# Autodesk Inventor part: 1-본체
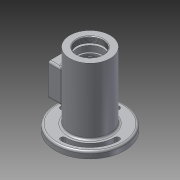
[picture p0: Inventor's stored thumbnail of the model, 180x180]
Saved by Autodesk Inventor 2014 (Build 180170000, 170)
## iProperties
Created: 2017-05
Part Number: 1-본체
Material: Aluminum 6061
Document SubType Name: Modeling
Designer: Administrator
Density: 2.71 g/cm^3
Appearance: Aluminum - Flat
Author: Administrator
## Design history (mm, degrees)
sketch "Sketch3"
  geometry: C1 r 31 at (0, 0); 1 further point
  constraints: 1 centre point, 1 coincident
  dimensions: "d0" = 62 diameter of C1
extrude "Extrusion1" new body sketch "Sketch3" distance "d1" = 115; taper "d2" = 0 deg
workplane "Work Plane1"
sketch "Sketch4"
  geometry: L1 (0, 34)-(44, 34); L2 (44, 34)-(44, 84); L3 (44, 84)-(0, 84); L4 (0, 84)-(0, 34); L5 (31, 115)-(-31, 115) reference; 2 further points
  constraints: 8 end point, 2 parallel, 1 horizontal, 1 midpoint, 1 perpendicular, 1 vertical alignment
  dimensions: "d4" = 50 distance of L1.end L2.end; "d5" = 44 distance of L2.end L3.end; "d6" = 56 distance from line of L5 point (0, 59)
extrude "Extrusion2" join sketch "Sketch4" stored distance "d7" = 40; taper "d8" = 0 deg
sketch "Sketch5"
  geometry: L1 (-44, -34)-(-44, -84) reference; L2 (-31, -115)-(31, -115) reference; 2 further points
  constraints: 1 other
  dimensions: "d9" = 56 distance from line of L2 point (-36, -59); "d10" = 8 distance from line of L1 point (-36, -59)
emboss "Emboss1" sketch "Sketch5" dims "d11" = 0.5, "d12" = 0
workplane "Work Plane2"
sketch "Sketch7"
  geometry: C1 r 53 at (0, 0); 1 further point
  constraints: 1 centre point, 1 coincident
  dimensions: "d14" = 106 diameter of C1
extrude "Extrusion3" join sketch "Sketch7" distance "d15" = 10; taper "d16" = 0 deg
sketch "Sketch8"
  geometry: L1 (0, -20.305)-(0, 135.116); L2 (22, 0)-(16, 14); L3 (16, 14)-(12.5, 14); L4 (12.5, 14)-(12.5, 21.3); L5 (12.5, 21.3)-(10, 21.3); L6 (10, 21.3)-(10, 24); L7 (10, 24)-(16.5, 24); L8 (16.5, 24)-(16.5, 29); L9 (16.5, 29)-(17.5, 29); L10 (17.5, 29)-(17.5, 40); L11 (17.5, 40)-(26, 40); L12 (22, 0)-(0, 0); L13 (26, 40)-(26, 78); L14 (26, 78)-(17.5, 78); L15 (17.5, 78)-(17.5, 89); L16 (17.5, 89)-(18.5, 89); L17 (18.5, 89)-(18.5, 90.75); L18 (18.5, 90.75)-(17.5, 90.75); L19 (17.5, 90.75)-(17.5, 94); L20 (17.5, 94)-(20, 94); L21 (20, 94)-(20, 103); L22 (20, 103)-(24, 103); L23 (24, 103)-(24, 106); L24 (24, 106)-(0, 106); L25 (31, 115)-(-31, 115) reference
  constraints: 48 end point, 13 perpendicular, 9 parallel, 2 point on line, 1 vertical
  dimensions: "d17" = 44 diameter of L2.start L1; "d18" = 32 diameter of L2.end L1; "d19" = 14 vertical distance of L2.start L2.end; "d20" = 7.3 distance of L3.end L4.end; "d21" = 2.7 distance of L5.end L6.end; "d22" = 25 diameter of L4 L1; "d23" = 20 diameter of L6 L1; "d24" = 35 diameter of L10 L1; "d25" = 11 distance of L9.end L10.end; "d26" = 5 distance of L7.end L8.end; "d27" = 38 distance of L11.end L13.end; "d28" = 35 diameter of L15 L1; "d29" = 1.75 distance of L16.end L17.end; "d30" = 37 diameter of L17 L1; "d31" = 11 distance of L14.end L15.end; "d32" = 33 diameter of L8 L1; "d33" = 52 diameter of L13 L1; "d34" = 35 diameter of L19 L1; "d35" = 48 diameter of L23 L1; "d36" = 40 diameter of L21 L1; "d37" = 3 distance of L22.end L23.end; "d91" = 12 distance from line of L25 L22.end; "d93" = 21 distance from line of L25 L20.end
revolve "Revolution1" sketch "Sketch8" stored, may be unused: angle "d40" = 90 deg
sketch "Sketch9"
  geometry: C1 r 31 at (0, 0) reference; 1 further point
  constraints: 1 coincident
hole "Hole1" sketch "Sketch9" at (0, 0) diameter "d41" = 40.376; stored, may be unused: countersink angle "d45" = 90 deg, drill point angle "d47" = 0 deg; dims "d42" = 9, "d43" = 4, "d44" = 2, "d46" = 9
sketch "Sketch10"
  geometry: L1 (0, 0)-(0, 40) reference; L2 (-50, 0)-(-50, 40) reference; L3 (0, 0)-(-50, 0) reference; L4 (-25, 69.012)-(-25, -33.786); L5 (-50, 20)-(0, 20); L6 (31, -11)-(31, 51) reference; L7 (-4.5, 4.5)-(-45.5, 4.5); L8 (-45.5, 4.5)-(-45.5, 35.5); L9 (-45.5, 35.5)-(-4.5, 35.5); L10 (-4.5, 35.5)-(-4.5, 4.5); L11 (-4.5, 4.5)-(-45.5, 35.5); L12 (-45.5, 4.5)-(-4.5, 35.5); 6 further points
  constraints: 16 end point, 5 midpoint, 4 coincident, 2 parallel, 2 perpendicular, 1 horizontal
  dimensions: "d48" = 56 distance between parallel lines of L6 L4; "d49" = 41 distance of L8.end L9.end; "d50" = 31 distance of L7.end L8.end
hole "Hole2" sketch "Sketch10" at (-45.5, 35.5), (-45.5, 4.5), (-4.5, 4.5), (-4.5, 35.5) diameter "d51" = 2.459; stored, may be unused: countersink angle "d55" = 90 deg, drill point angle "d57" = 118 deg; dims "d52" = 6, "d53" = 4, "d54" = 2, "d56" = 8
sketch "Sketch11"
  geometry: L1 (-50, 40)-(0, 0); L2 (-41, 9)-(-9, 9); L3 (-9, 9)-(-9, 31); L4 (-9, 31)-(-41, 31); L5 (-41, 31)-(-41, 9); L6 (-41, 9)-(-9, 31); L7 (-9, 9)-(-41, 31); 2 further points
  constraints: 14 end point, 3 midpoint, 2 parallel, 1 horizontal, 1 perpendicular
  dimensions: "d58" = 22 distance of L2.end L3.end; "d59" = 32 distance of L3.end L4.end
extrude "Extrusion4" cut sketch "Sketch11" stored distance "d60" = 13; taper "d61" = 0 deg
fillet "Fillet1" dims "d65" = 3
fillet "Fillet2" dims "d66" = 3
fillet "Fillet3" dims "d67" = 0.3
fillet "Fillet4" dims "d68" = 0.3
chamfer "Chamfer2" distance "d69" = 0.7; stored, may be unused: second distance "d70" = 2, angle "d71" = 30 deg
fillet "Fillet5" dims "d72" = 3
sketch "Sketch12"
  geometry: C1 r 31 at (0, 0) reference; A1 r 41.5 centre (0, 0) between (41.5, 0) and (0, 41.5); A2 r 41.5 centre (0, 0) between (41.5, 0) and (0, 41.5); A3 r 45.5 centre (0, 0) between (45.5, 0) and (0, 45.5); A4 r 37.5 centre (0, 0) between (37.5, 0) and (0, 37.5); A5 r 4 centre (41.5, 0) between (37.5, 0) and (45.5, 0); A6 r 4 centre (0, 41.5) between (0, 45.5) and (0, 37.5); A7 r 41.5 centre (0, 0) between (-41.5, 0) and (0, -41.5); A8 r 45.5 centre (0, 0) between (-45.5, 0) and (0, -45.5); A9 r 37.5 centre (0, 0) between (-37.5, 0) and (0, -37.5); A10 r 4 centre (-41.5, 0) between (-37.5, 0) and (-45.5, 0); A11 r 4 centre (0, -41.5) between (0, -45.5) and (0, -37.5)
  constraints: 24 point on circle, 11 centre point, 10 tangent, 1 coincident
  dimensions: "d73" = 83 diameter of A1; "d74" = 4 radius of A5; "d78" = 4 radius of A10
extrude "Extrusion5" cut sketch "Sketch12" stored distance "d79" = 13; taper "d80" = 0 deg
fillet "Fillet6" dims "d81" = 3
fillet "Fillet7" dims "d82" = 3
fillet "Fillet8" dims "d83" = 3
chamfer "Chamfer3" distance "d84" = 1; stored, may be unused: second distance "d85" = 2, angle "d86" = 30 deg
fillet "Fillet9" dims "d87" = 3
chamfer "Chamfer4" distance "d88" = 1; stored, may be unused: second distance "d89" = 2, angle "d90" = 30 deg
body "Solid1"
other parameters: "d3" = 0, "d13" = -3
